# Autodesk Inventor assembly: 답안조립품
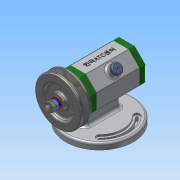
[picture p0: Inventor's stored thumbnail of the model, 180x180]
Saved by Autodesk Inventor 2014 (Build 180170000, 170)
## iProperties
Created: 2017-06
Part Number: 답안조립품
Document SubType Name: Assembly
Designer: NET
Author: NET
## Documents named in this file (14)
- C:\Users\NET\Desktop\470607V1016\답안조립품.iam
- C:\Users\NET\Desktop\470607V1016\본체.ipt
- C:\Users\NET\Desktop\470607V1016\뒤커버.ipt
- C:\Users\NET\Desktop\470607V1016\앞커버.ipt
- C:\Users\NET\Desktop\470607V1016\베어링 15 x 32 x 9.ipt
- C:\Users\NET\Desktop\470607V1016\오일 실 15 25 7.ipt
- C:\Users\NET\Desktop\470607V1016\축.ipt
- C:\Users\NET\Desktop\470607V1016\키 3 x 3 x 12.ipt
- C:\Users\NET\Desktop\470607V1016\볼트 M4 x 12.ipt
- C:\Users\NET\Desktop\470607V1016\고무캡.ipt
- C:\Users\NET\Desktop\470607V1016\V벨트풀리.ipt
- C:\Users\NET\Desktop\470607V1016\너트 M 8.ipt
- C:\Users\NET\Desktop\470607V1016\스프링와셔 8.ipt
- C:\Users\NET\Desktop\470607V1016\와셔 8x17.ipt
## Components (2 placed, 2 different names)
1. 고무캡:1
2. V벨트풀리:1
